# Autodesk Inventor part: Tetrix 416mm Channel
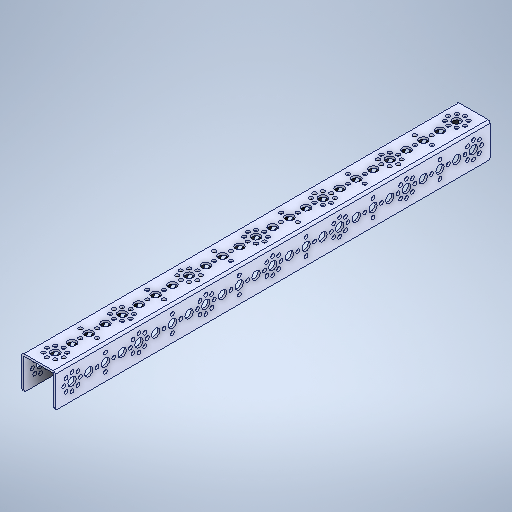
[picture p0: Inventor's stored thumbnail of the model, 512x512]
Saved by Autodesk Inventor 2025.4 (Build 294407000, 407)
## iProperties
Created: 2021-10
Part Number: Tetrix 416mm Channel
Material: Genérico
Document SubType Name: Modeling
Designer: usuario
Density: 1 g/cm^3
Appearance: Valor por defecto
Author: usuario
Sending System: SolidWorks 2016
Last Author: LENOVO
Last Saved: 2021-10-21
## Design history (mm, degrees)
fillet "Fillet1"
node "Plane1"
node "Sólido1"
